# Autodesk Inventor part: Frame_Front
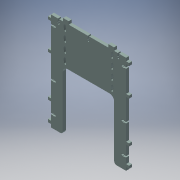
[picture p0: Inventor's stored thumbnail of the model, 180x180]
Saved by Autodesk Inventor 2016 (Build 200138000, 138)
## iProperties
Created: 2015-11
Part Number: Frame_Front
Material: Generic
Document SubType Name: Modeling
Designer: John
Density: 1 g/cm^3
Appearance: Default
Author: John
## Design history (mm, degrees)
feature "SOLID1"
node "Direct Edit1"
sketch "Sketch1"
  geometry: L1 (-20, -237.3)-(-20, -20) reference; L2 (0, 0)-(175.9, 0) reference; L3 (195.9, -20)-(195.9, -237.3) reference; L4 (205.9, -247.3)-(245.9, -247.3) reference; L5 (245.9, -247.3)-(245.9, -233.8) reference; L6 (245.9, -233.8)-(258.6, -233.8) reference; L7 (258.6, -233.8)-(258.6, -222.7) reference; L8 (258.6, -222.7)-(245.9, -222.7) reference; L9 (245.9, -222.7)-(245.9, -199.125) reference; L10 (245.9, -199.125)-(238.7, -199.125) reference; L11 (238.7, -199.125)-(238.7, -200.625) reference; L12 (238.7, -200.625)-(231.7, -200.625) reference; L13 (231.7, -200.625)-(231.7, -199.125) reference; L14 (231.7, -199.125)-(225.7, -199.125) reference; L15 (225.7, -199.125)-(225.7, -193.875) reference; L16 (225.7, -193.875)-(231.7, -193.875) reference; L17 (231.7, -193.875)-(231.7, -192.375) reference; L18 (231.7, -192.375)-(238.7, -192.375) reference; L19 (238.7, -192.375)-(238.7, -193.875) reference; L20 (238.7, -193.875)-(245.9, -193.875) reference; L21 (245.9, -193.875)-(245.9, -152.45) reference; L22 (245.9, -152.45)-(258.6, -152.45) reference; L23 (258.6, -152.45)-(258.6, -141.35) reference; L24 (258.6, -141.35)-(245.9, -141.35) reference; L25 (245.9, -141.35)-(245.9, -74.925) reference; L26 (245.9, -74.925)-(238.7, -74.925) reference; L27 (238.7, -74.925)-(238.7, -76.425) reference; L28 (238.7, -76.425)-(231.7, -76.425) reference; L29 (231.7, -76.425)-(231.7, -74.925) reference; L30 (231.7, -74.925)-(225.7, -74.925) reference; L31 (225.7, -74.925)-(225.7, -69.675) reference; L32 (225.7, -69.675)-(231.7, -69.675) reference; L33 (231.7, -69.675)-(231.7, -68.175) reference; L34 (231.7, -68.175)-(238.7, -68.175) reference; L35 (238.7, -68.175)-(238.7, -69.675) reference; L36 (238.7, -69.675)-(245.9, -69.675) reference; L37 (245.9, -69.675)-(245.9, 21.75) reference; L38 (245.9, 21.75)-(258.6, 21.75) reference; L39 (258.6, 21.75)-(258.6, 32.85) reference; L40 (258.6, 32.85)-(245.9, 32.85) reference; L41 (245.9, 32.85)-(245.9, 124.275) reference; L42 (245.9, 124.275)-(238.7, 124.275) reference; L43 (238.7, 124.275)-(238.7, 122.775) reference; L44 (238.7, 122.775)-(231.7, 122.775) reference; L45 (231.7, 122.775)-(231.7, 124.275) reference; L46 (231.7, 124.275)-(225.7, 124.275) reference; L47 (225.7, 124.275)-(225.7, 129.525) reference; L48 (225.7, 129.525)-(231.7, 129.525) reference; L49 (231.7, 129.525)-(231.7, 131.025) reference; L50 (231.7, 131.025)-(238.7, 131.025) reference; L51 (238.7, 131.025)-(238.7, 129.525) reference; L52 (238.7, 129.525)-(245.9, 129.525) reference; L53 (245.9, 129.525)-(245.9, 140.4) reference; L54 (245.9, 140.4)-(258.6, 140.4) reference; L55 (258.6, 140.4)-(258.6, 151.5) reference; L56 (258.6, 151.5)-(245.9, 151.5) reference; L57 (245.9, 151.5)-(245.9, 164.2) reference; L58 (245.9, 164.2)-(216.125, 164.2) reference; L59 (216.125, 164.2)-(216.125, 157) reference; L60 (216.125, 157)-(217.625, 157) reference; L61 (217.625, 157)-(217.625, 150) reference; L62 (217.625, 150)-(216.125, 150) reference; L63 (216.125, 150)-(216.125, 144) reference; L64 (216.125, 144)-(210.875, 144) reference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; A1 r 10 centre (-30, -237.3) between (-30, -247.3) and (-20, -237.3) reference; A2 r 20 centre (0, -20) between (0, 0) and (-20, -20) reference; A3 r 20 centre (175.9, -20) between (195.9, -20) and (175.9, 0) reference; A4 r 10 centre (205.9, -237.3) between (195.9, -237.3) and (205.9, -247.3) reference; A5 r 104.25 centre (87.95, 73) between (-16.3, 73) and (-14.716, 54.897) reference; A6 r 4.25 centre (-12.05, 73) between (-7.8, 73) and (-16.3, 73) reference; A7 r 95.75 centre (87.95, 73) between (-7.8, 73) and (-6.345, 56.373) reference; A8 r 4.25 centre (-10.531, 55.635) between (-14.716, 54.897) and (-6.345, 56.373) reference; A9 r 4.25 centre (187.95, 33) between (192.2, 33) and (183.7, 33) reference; A10 r 104.25 centre (87.95, 33) between (190.616, 14.897) and (192.2, 33) reference; A11 r 4.25 centre (186.431, 15.635) between (182.245, 16.373) and (190.616, 14.897) reference; A12 r 95.75 centre (87.95, 33) between (182.245, 16.373) and (183.7, 33) reference; A13 r 4.25 centre (-10.531, 15.635) between (-14.716, 14.897) and (-6.345, 16.373) reference; A14 r 104.25 centre (87.95, 33) between (-16.3, 33) and (-14.716, 14.897) reference; A15 r 4.25 centre (-12.05, 33) between (-7.8, 33) and (-16.3, 33) reference; A16 r 95.75 centre (87.95, 33) between (-7.8, 33) and (-6.345, 16.373) reference; A17 r 4.25 centre (186.431, 95.635) between (182.245, 96.373) and (190.616, 94.897) reference; A18 r 95.75 centre (87.95, 113) between (182.245, 96.373) and (183.7, 113) reference; A19 r 4.25 centre (187.95, 113) between (192.2, 113) and (183.7, 113) reference; A20 r 104.25 centre (87.95, 113) between (190.616, 94.897) and (192.2, 113) reference; A21 r 4.25 centre (-12.05, 113) between (-7.8, 113) and (-16.3, 113) reference; A22 r 95.75 centre (87.95, 113) between (-7.8, 113) and (-6.345, 96.373) reference; A23 r 4.25 centre (-10.531, 95.635) between (-14.716, 94.897) and (-6.345, 96.373) reference; A24 r 104.25 centre (87.95, 113) between (-16.3, 113) and (-14.716, 94.897) reference; A25 r 4.25 centre (-12.05, 153) between (-7.8, 153) and (-16.3, 153) reference; A26 r 95.75 centre (87.95, 153) between (-7.8, 153) and (-6.345, 136.373) reference; A27 r 4.25 centre (-10.531, 135.635) between (-14.716, 134.897) and (-6.345, 136.373) reference; A28 r 104.25 centre (87.95, 153) between (-16.3, 153) and (-14.716, 134.897) reference; A29 r 4.25 centre (186.431, 135.635) between (182.245, 136.373) and (190.616, 134.897) reference; A30 r 95.75 centre (87.95, 153) between (182.245, 136.373) and (183.7, 153) reference; A31 r 4.25 centre (187.95, 153) between (192.2, 153) and (183.7, 153) reference; A32 r 104.25 centre (87.95, 153) between (190.616, 134.897) and (192.2, 153) reference; A33 r 4.25 centre (186.431, 55.635) between (182.245, 56.373) and (190.616, 54.897) reference; A34 r 95.75 centre (87.95, 73) between (182.245, 56.373) and (183.7, 73) reference; A35 r 4.25 centre (187.95, 73) between (192.2, 73) and (183.7, 73) reference; A36 r 104.25 centre (87.95, 73) between (190.616, 54.897) and (192.2, 73) reference; A37 r 25.45 centre (175.9, 25.45) between (150.45, 25.45) and (175.9, 0); A38 r 25.45 centre (0, 25.45) between (0, 0) and (25.45, 25.45); A39 r 20 centre (175.9, -20) between (195.9, -20) and (175.9, 0) reference; A40 r 20 centre (0, -20) between (0, 0) and (-20, -20) reference; 3 further points
  constraints: 8 end point, 4 point on circle, 3 tangent, 2 centre point, 2 midpoint, 2 parallel, 1 equal radius, 1 horizontal, 1 horizontal alignment, 1 perpendicular, 1 vertical alignment
  dimensions: "d6" = 125 distance of L158.end L159.end; "d7" = 75 distance of L159.end L157.start
extrude "Extrusion1" cut sketch "Sketch1" stored distance "d8" = 10; taper "d9" = 0 deg
fillet "Fillet1" dims "d10" = 10
body "Solid1"
node "Projected Loop1"
move_body "Move1"
move_body "Move2" dims "d3" = 25
other parameters: "d0" = 0, "d1" = 0, "d4" = 0, "d5" = 0
